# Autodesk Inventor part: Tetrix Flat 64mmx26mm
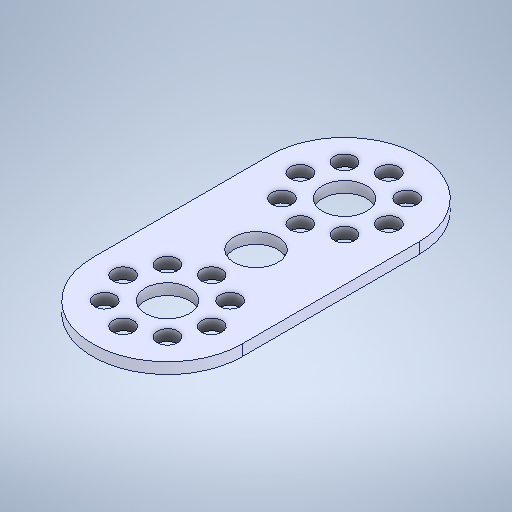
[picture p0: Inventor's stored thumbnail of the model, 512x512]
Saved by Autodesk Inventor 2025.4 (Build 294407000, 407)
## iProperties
Created: 2021-10
Part Number: Tetrix Flat 64mmx26mm
Material: Genérico
Document SubType Name: Modeling
Designer: usuario
Density: 1 g/cm^3
Appearance: Valor por defecto
Author: usuario
Sending System: SolidWorks 2016
Last Author: LENOVO
Last Saved: 2021-10-23
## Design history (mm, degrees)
feature "Boss-Extrude1"
node "Plane1"
node "Sólido1"
